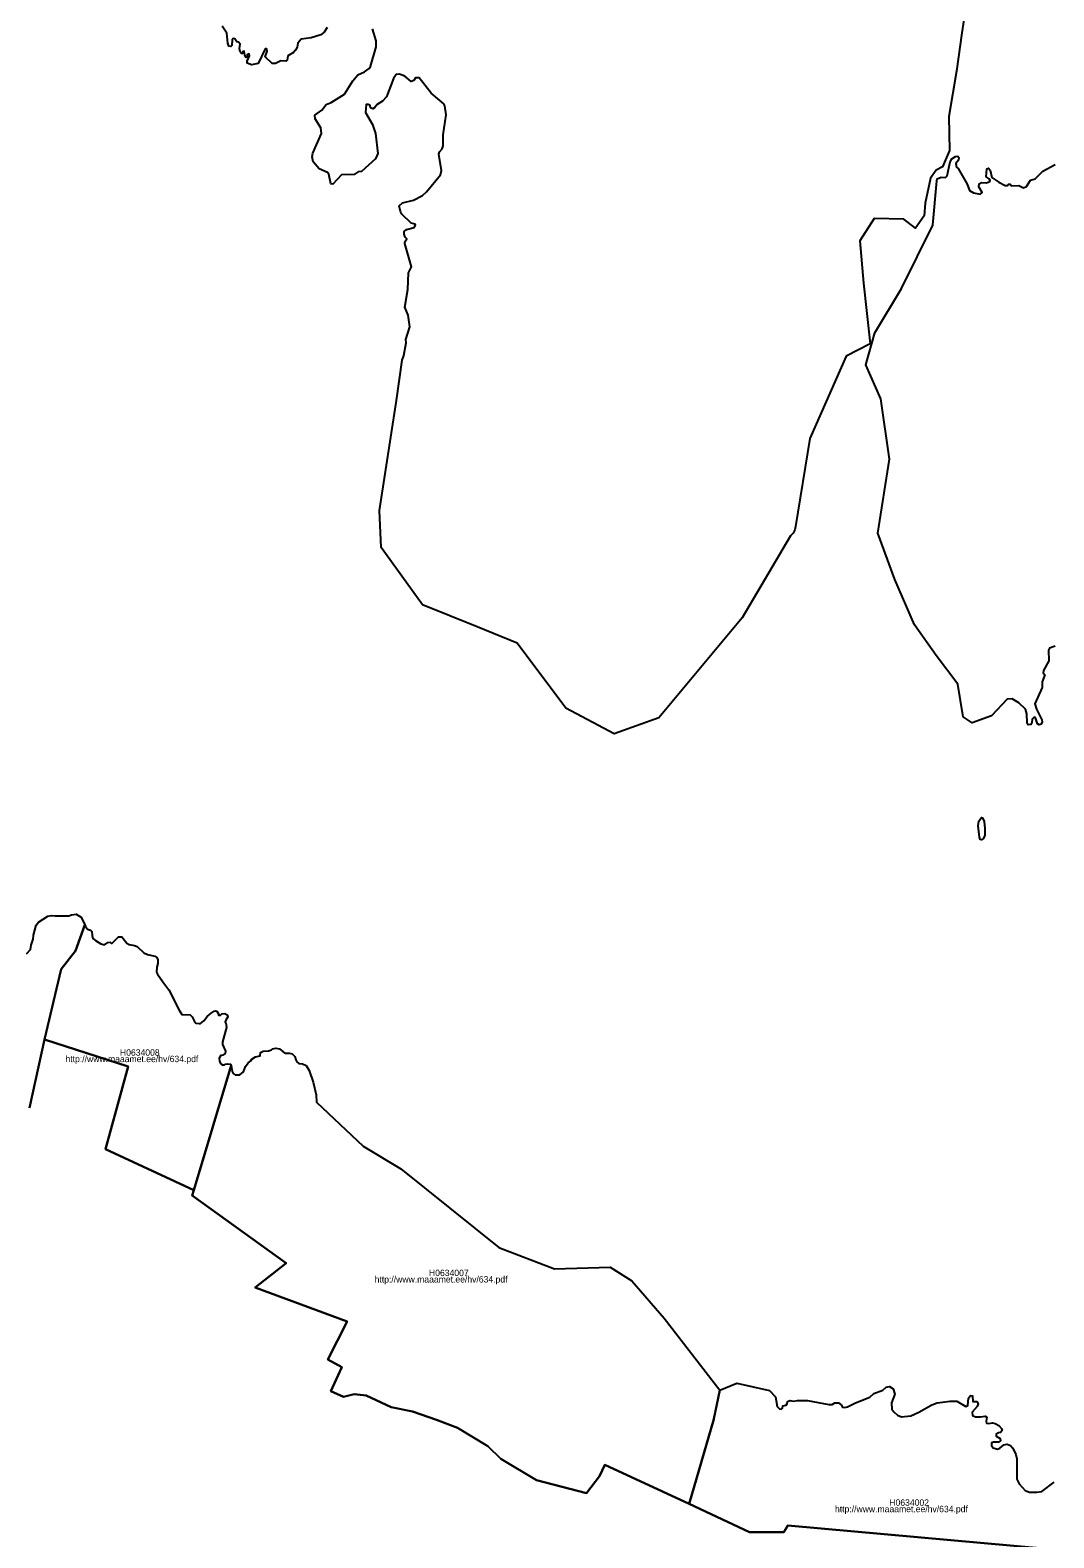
# Model space of a CAD drawing. Extents: x 369010 to 739155, y 6377141 to 6634081.
# Drawn here: x 452935 to 456915, y 6483613 to 6489475 of the extents above; entities that cross this region are included whole.
import ezdxf

# ---------------------------------------------------------------- set-up
doc = ezdxf.new("R2010")
doc.units = 0
for name, color, linetype in [('H_LINK', 7, 'Continuous'), ('H_PIIR', 7, 'Continuous'), ('H_TUNNUS', 7, 'Continuous')]:
    doc.layers.add(name, color=color, linetype=linetype)

msp = doc.modelspace()

# ---------------------------------------------------------------- linework, layer by layer
at = {"layer": 'H_PIIR'}
for points in [[(456585.5297, 6489652.0638), (456556.9546, 6489464.7385), (456536.3171, 6489315.5132), (456506.1545, 6489139.3003), (456508.74, 6489007.06), (456482.342, 6488944.0374), (456456.9419, 6488931.3374), (456434.7169, 6488899.5873), (456414.8026, 6488803.0723), (456410.9725, 6488753.5823), (456377.5668, 6488705.9119), (456331.5292, 6488740.837), (456215.6415, 6488742.4245), (456160.0788, 6488656.6993), (456174.3664, 6488491.599), (456200.86, 6488255.74), (456107.84, 6488207.24), (455966.4035, 6487887.554), (455910.7401, 6487545.0001), (455908.18, 6487532.1699), (455901.12, 6487519.33), (455891.18, 6487509.39), (455703.1425, 6487190.6402), (455379.2919, 6486801.1727), (455205.7249, 6486739.7893), (455017.3411, 6486839.2728), (454828.9574, 6487091.1566), (454672.3238, 6487154.6567), (454460.6567, 6487241.4403), (454299.7897, 6487463.6907), (454293.4397, 6487607.6243), (454359.0565, 6488035.1918), (454380.75, 6488191.7801), (454388.1201, 6488209.74), (454396.1401, 6488259.7901), (454394.8599, 6488271.9801), (454411.2201, 6488321.3899), (454404.49, 6488367.5899), (454391.9699, 6488398.38), (454403.84, 6488467.04), (454406.4099, 6488531.2), (454417.9599, 6488554.6201), (454391.33, 6488645.42), (454391.65, 6488652.48), (454399.35, 6488663.7001), (454392.6199, 6488670.1201), (454388.77, 6488681.99), (454389.41, 6488692.26), (454397.7499, 6488699.64), (454427.2601, 6488708.6199), (454433.6801, 6488716.96), (454431.7599, 6488720.49), (454416.68, 6488725.2999), (454379.78, 6488759.9499), (454374.6499, 6488769.58), (454369.84, 6488791.7099), (454382.67, 6488803.9001), (454424.7, 6488814.8099), (454460.31, 6488832.46), (454475.7099, 6488846.5701), (454530.89, 6488912.3401), (454534.1001, 6488929.0199), (454523.83, 6488992.5501), (454526.72, 6489002.8099), (454536.9901, 6489013.4001), (454540.19, 6489025.9099), (454540.52, 6489068.26), (454552.71, 6489145.8999), (454547.2499, 6489181.1899), (454543.08, 6489188.2501), (454493.6801, 6489230.6), (454447.8, 6489289.31), (454433.0401, 6489289.31), (454426.3, 6489280), (454415.7201, 6489275.8299), (454391.0101, 6489296.6901), (454370.8001, 6489304.0599), (454358.29, 6489302.4601), (454348.02, 6489287.06), (454320.4299, 6489216.4801), (454304.71, 6489198.84), (454283.86, 6489186.64), (454273.91, 6489172.85), (454267.82, 6489169.32), (454257.87, 6489173.1701), (454256.27, 6489182.15), (454249.5299, 6489186.3199), (454241.5101, 6489186.3199), (454239.2601, 6489155.52), (454265.89, 6489108.68), (454277.1199, 6489073.3901), (454286.1, 6488995.76), (454277.44, 6488975.2199), (454223.5399, 6488925.4999), (454209.7501, 6488924.85), (454194.35, 6488913.9499), (454145.9, 6488912.66), (454112.2199, 6488877.0499), (454104.52, 6488877.37), (454095.5401, 6488915.55), (454090.72, 6488922.29), (454058.6401, 6488936.72), (454035.22, 6488962.71), (454031.05, 6488982.28), (454033.62, 6488996.4), (454068.2599, 6489074.04), (454064.4201, 6489095.2099), (454042.9199, 6489130.5001), (454041.3201, 6489144.9401), (454068.59, 6489164.19), (454085.91, 6489186.3199), (454105.16, 6489193.7), (454156.49, 6489226.7499), (454188.8999, 6489277.76), (454209.1099, 6489301.1799), (454235.41, 6489313.69), (454252.4199, 6489326.2), (454258.51, 6489334.54), (454279.69, 6489410.9001), (454280.6499, 6489434.0001), (454266.2099, 6489480.2001)], [(454090.08, 6489485.65), (454077.89, 6489467.04), (454065.3799, 6489457.1001), (454026.8801, 6489444.9001), (453988.38, 6489440.41), (453975.87, 6489425.3401), (453972.6601, 6489409.6199), (453966.2399, 6489397.42), (453958.8601, 6489389.08), (453937.3699, 6489375.6099), (453934.16, 6489359.25), (453929.9901, 6489354.11), (453910.1, 6489356.36), (453888.9299, 6489345.45), (453876.41, 6489345.1301), (453849.1401, 6489371.44), (453856.84, 6489393.5701), (453855.5601, 6489401.27), (453852.35, 6489403.2), (453848.18, 6489402.56), (453821.23, 6489345.45), (453795.25, 6489340), (453779.1999, 6489347.3801), (453778.2401, 6489354.43), (453788.19, 6489375.6099), (453786.9001, 6489382.34), (453782.0899, 6489383.6299), (453778.88, 6489381.06), (453777.6001, 6489370.15), (453774.7101, 6489369.51), (453769.9, 6489377.53), (453766.6901, 6489393.5701), (453761.8799, 6489392.9299), (453759.96, 6489383.95), (453756.7499, 6489383.95), (453751.87, 6489390.83), (453748.7301, 6489403.8399), (453751.29, 6489421.49), (453745.1999, 6489428.2201), (453738.78, 6489429.51), (453730.7599, 6489442.0201), (453724.34, 6489443.3), (453719.8499, 6489437.21), (453718.89, 6489415.71), (453715.68, 6489411.86), (453707.6599, 6489413.46), (453703.49, 6489425.02), (453699.6399, 6489463.51), (453681.03, 6489490.78)], [(456920.2999, 6487080.68), (456897.62, 6487072.7), (456893.7899, 6487065.04), (456895.39, 6487023.1999), (456874.3101, 6486985.1999), (456873.35, 6486976.5801), (456879.4199, 6486968.6001), (456869.84, 6486940.8201), (456869.2, 6486919.74), (456840.7801, 6486856.5199), (456847.49, 6486835.44), (456867.61, 6486793.29), (456868.88, 6486786.2701), (456865.0501, 6486777.0001), (456857.71, 6486774.45), (456851, 6486778.5999), (456843.98, 6486800.95), (456838.5501, 6486803.5101), (456829.9101, 6486796.87), (456829.55, 6486783.2399), (456825.46, 6486775.7299), (456815.56, 6486773.81), (456811.08, 6486781.8), (456809.17, 6486816.92), (456804.06, 6486835.44), (456778.5101, 6486859.3899), (456752.33, 6486875.6801), (456733.17, 6486874.08), (456672.8424, 6486808.8456), (456596.6422, 6486781.8581), (456561.7172, 6486805.6706), (456541.0796, 6486932.6709), (456456.9419, 6487043.7961), (456372.8043, 6487162.8588), (456296.6041, 6487339.0717), (456229.929, 6487520.0471), (456275.9666, 6487807.3851), (456242.629, 6488042.3356), (456183.8914, 6488174.0984), (456218.8165, 6488297.9236), (456322.0042, 6488470.9615), (456444.2419, 6488717.0245), (456460.4699, 6488889.3401), (456461.42, 6488897), (456476.43, 6488903.39), (456493.04, 6488901.8), (456500.3801, 6488909.4601), (456511.8799, 6488962.79), (456518.2601, 6488974.5999), (456531.9999, 6488984.5001), (456541.2599, 6488984.82), (456545.4301, 6488980.26), (456544.45, 6488970.1301), (456533.95, 6488956.58), (456536.1501, 6488942.9901), (456543.27, 6488937.92), (456577.34, 6488875.9299), (456587.04, 6488851.8101), (456602.89, 6488842.72), (456627.7899, 6488837.9301), (456635.65, 6488844.63), (456622.7301, 6488866.52), (456623.96, 6488877.84), (456633.86, 6488882.67), (456652.38, 6488881.36), (456665.4701, 6488887.11), (456666.75, 6488890.9399), (456663.27, 6488897.3801), (456651.4299, 6488905.27), (456653.7699, 6488936.42), (456660.35, 6488938.17), (456666.7, 6488930.7099), (456674.1001, 6488901.8), (456700.92, 6488884.23), (456725.51, 6488871.78), (456734.1301, 6488871.78), (456737.9599, 6488876.89), (456744.3499, 6488876.5701), (456750.7299, 6488869.5399), (456778.2, 6488871.14), (456797.04, 6488861.88), (456808.85, 6488867.9501), (456824.18, 6488891.9), (456842.3799, 6488896.6899), (456871.4401, 6488927.02), (456919.3401, 6488953.2099)], [(452921.3299, 6485883.4647), (452935.7601, 6485900.4746), (452938.6501, 6485917.7946), (452946.6699, 6485940.8946), (452948.28, 6485956.2946), (452957.9, 6485994.7947), (452966.8799, 6486006.6646), (453003.46, 6486030.4047), (453017.5699, 6486032.9646), (453031.69, 6486031.0447), (453085.2701, 6486031.0447), (453095.21, 6486035.8546), (453113.82, 6486038.1047), (453133.0699, 6486026.8746), (453146.8989, 6485996.6055), (453111.2501, 6485896.06), (453056.02, 6485823.7801), (452990.1101, 6485550.08), (452932.49, 6485285.4801)], [(452932.49, 6485285.4801), (452990.1101, 6485550.08), (453316.0201, 6485445.2399), (453227.27, 6485123.9101), (453570.9099, 6484965.4), (453564.54, 6484944.17), (453930.4299, 6484681.3299), (453809.7, 6484586.4), (454167.7101, 6484454.0101), (454092.26, 6484306.65), (454147.27, 6484277.16), (454104.0499, 6484182.8099), (454153.1699, 6484161.19), (454194.45, 6484172.2), (454241.14, 6484165.84), (454338.77, 6484121.25), (454421.5401, 6484104.2599), (454514.9299, 6484072.42), (454595.99, 6484041.13), (454714.31, 6483969.17), (454764.92, 6483920.52), (454903.8901, 6483836.6199), (455097.3, 6483786.64), (455148.23, 6483852.46), (455169.46, 6483897.05), (455496.3699, 6483744.73), (455731.08, 6483635.3701), (455865.6901, 6483634.6901), (455880.86, 6483661.38), (456889.11, 6483570.5799)], [(456889.11, 6483570.5799), (455880.86, 6483661.38), (455865.6901, 6483634.6901), (455731.08, 6483635.3701), (455496.3699, 6483744.73), (455592.6399, 6484074.69), (455593.0409, 6484076.0639), (455616.7729, 6484187.3525), (455682.0458, 6484215.0545), (455809.28, 6484185.4446), (455832.1999, 6484161.4046), (455838.5499, 6484123.2946), (455847.62, 6484114.2247), (455854.88, 6484113.7647), (455859.8699, 6484116.9446), (455860.78, 6484126.9247), (455874.3801, 6484128.7347), (455878.4701, 6484135.0947), (455879.83, 6484142.8046), (455890.26, 6484147.3447), (455900.7, 6484144.6146), (455917.93, 6484147.3447), (455957.17, 6484146.8846), (456040.18, 6484131.0047), (456052.43, 6484131.0047), (456063.77, 6484138.2646), (456076.9301, 6484138.2646), (456088.04, 6484130.5547), (456093.4899, 6484121.4846), (456102.11, 6484119.2146), (456112.0901, 6484121.9347), (456143.8401, 6484138.2746), (456199.91, 6484160.6246), (456214.62, 6484173.7847), (456250.0401, 6484187.3346), (456263.1999, 6484199.3346), (456275.58, 6484201.6546), (456289.9, 6484191.9746), (456296.48, 6484172.2346), (456284.1001, 6484138.1746), (456285.26, 6484113.7847), (456292.22, 6484102.9446), (456307.32, 6484089.7846), (456322.41, 6484083.2047), (456359.38, 6484087.4646), (456390.34, 6484101.0147), (456441.0401, 6484130.4347), (456461.7501, 6484137.3947), (456511.68, 6484144.3647), (456537.2199, 6484143.9746), (456572.06, 6484123.8546), (456580.96, 6484127.3346), (456583.28, 6484156.3647), (456590.4401, 6484166.4246), (456598.18, 6484165.2646), (456600.1199, 6484143.2047), (456614.83, 6484142.8146), (456621.0201, 6484133.9147), (456616.76, 6484123.4647), (456597.02, 6484101.3946), (456598.57, 6484088.6246), (456610.5701, 6484083.9746), (456629.15, 6484083.2047), (456648.1101, 6484085.9146), (456654.69, 6484081.6546), (456651.21, 6484066.1746), (456652.37, 6484059.2046), (456660.5, 6484058.0446), (456676.3701, 6484060.3646), (456687.1999, 6484057.6546), (456700.75, 6484049.9146), (456710.81, 6484037.9146), (456713.9101, 6484029.7846), (456707.72, 6484022.8146), (456699.59, 6484020.8847), (456691.07, 6484016.6246), (456690.3, 6484008.4946), (456706.17, 6483998.8147), (456707.91, 6483990.6846), (456699.01, 6483985.6547), (456680.4301, 6483985.2646), (456671.92, 6483982.9446), (456672.3001, 6483972.4947), (456678.5, 6483962.8146), (456695.14, 6483958.1746), (456705.2001, 6483961.2646), (456720.3001, 6483974.8147), (456733.84, 6483976.7546), (456745.84, 6483971.7247), (456755.8999, 6483961.6546), (456767.5101, 6483936.4946), (456771.38, 6483919.8547), (456771.19, 6483841.2746), (456780.48, 6483823.0747), (456803.7, 6483796.7546), (456819.9599, 6483790.5647), (456848.6, 6483790.5647), (456867.57, 6483793.6547), (456916.52, 6483828.8746)]]:
    msp.add_lwpolyline(points, dxfattribs=at)
for points in [[(456641.2001, 6486332.5), (456633.22, 6486326.76), (456628.75, 6486328.35), (456625.88, 6486337.3001), (456620.4501, 6486382), (456622.6801, 6486399.88), (456632.9, 6486414.25), (456637.37, 6486412.9701), (456644.4, 6486398.6), (456646.9501, 6486371.7799), (456645.99, 6486345.6)], [(453146.8989, 6485996.6055), (453150.07, 6485989.6646), (453157.45, 6485979.0747), (453169, 6485976.1847), (453175.0999, 6485971.0547), (453175.7399, 6485955.6546), (453178.3, 6485943.7846), (453188.89, 6485935.1146), (453210.07, 6485923.2447), (453224.1799, 6485919.3946), (453236.7, 6485927.7447), (453246.32, 6485928.7046), (453250.1699, 6485925.1746), (453254.02, 6485924.8547), (453279.0399, 6485950.1947), (453290.91, 6485949.5546), (453310.48, 6485925.4947), (453319.79, 6485919.7247), (453340.64, 6485916.8347), (453350.5899, 6485912.3446), (453377.54, 6485887.9547), (453391.6501, 6485881.2246), (453419.8801, 6485874.1647), (453426.94, 6485869.3546), (453431.76, 6485860.3647), (453431.11, 6485846.5746), (453426.94, 6485832.4546), (453426.62, 6485812.8847), (453430.47, 6485804.2247), (453450.3599, 6485774.7046), (453473.78, 6485744.2347), (453514.21, 6485664.9846), (453524.47, 6485648.3046), (453556.5599, 6485646.7047), (453565.2199, 6485638.3546), (453571.95, 6485623.2846), (453578.69, 6485614.6147), (453591.8401, 6485612.3746), (453596.66, 6485613.3347), (453610.45, 6485623.6047), (453623.29, 6485640.2846), (453639.0099, 6485653.4346), (453650.88, 6485661.1347), (453657.29, 6485662.7446), (453660.18, 6485661.4546), (453668.2, 6485647.6646), (453667.24, 6485645.7347), (453675.26, 6485645.4146), (453680.39, 6485650.5546), (453691.94, 6485651.5147), (453701.24, 6485646.0546), (453703.1701, 6485638.3546), (453695.1501, 6485626.4847), (453693.55, 6485618.7846), (453695.47, 6485615.5847), (453698.68, 6485597.6146), (453682.64, 6485541.1547), (453682.3199, 6485531.5247), (453693.8699, 6485505.8646), (453692.9, 6485496.2347), (453684.24, 6485490.1446), (453676.86, 6485488.2147), (453669.6599, 6485478.0346), (453670.45, 6485464.7046), (453676.86, 6485456.1346), (453682.64, 6485452.2847), (453690.9799, 6485452.2847), (453693.54, 6485454.5246), (453703.49, 6485456.1346), (453713.4399, 6485454.8446), (453716.8899, 6485449.1999), (453570.9099, 6484965.4), (453227.27, 6485123.9101), (453316.0201, 6485445.2399), (452990.1101, 6485550.08), (453056.02, 6485823.7801), (453111.2501, 6485896.06)], [(453716.8912, 6485449.2036), (453716.9699, 6485449.0746), (453719.8499, 6485425.6546), (453724.0201, 6485418.5946), (453732.0401, 6485413.7847), (453750.01, 6485413.7847), (453764.7699, 6485425.0146), (453772.15, 6485445.5447), (453782.41, 6485459.3447), (453792.6801, 6485468.0047), (453796.5299, 6485474.4146), (453810.5701, 6485483.6546), (453828.9501, 6485487.4247), (453830.86, 6485499.7647), (453840.8, 6485505.5347), (453861.98, 6485506.8246), (453873.8499, 6485510.3546), (453877.3799, 6485513.8846), (453889.5701, 6485516.7646), (453904.33, 6485514.8446), (453919.08, 6485502.6547), (453928.0699, 6485498.1646), (453942.82, 6485498.1646), (453954.0499, 6485494.6346), (453963.68, 6485484.3646), (453967.21, 6485471.2146), (453971.3799, 6485464.1546), (453979.3999, 6485457.4146), (453993.51, 6485456.1346), (454007.63, 6485449.0746), (454020.14, 6485430.7846), (454035.86, 6485384.5846), (454046.77, 6485335.1847), (454048.6999, 6485306.9547), (454229.9601, 6485135.3146), (454376.051, 6485048.132), (454756.5314, 6484742.1055), (454974.0194, 6484659.5554), (455189.9198, 6484665.9054), (455274.0575, 6484611.9303), (455399.4702, 6484467.4675), (455616.7729, 6484187.3525), (455593.0409, 6484076.0639), (455592.6399, 6484074.69), (455496.3699, 6483744.73), (455169.46, 6483897.05), (455148.23, 6483852.46), (455097.3, 6483786.64), (454903.8901, 6483836.6199), (454764.92, 6483920.52), (454714.31, 6483969.17), (454595.99, 6484041.13), (454514.9299, 6484072.42), (454421.5401, 6484104.2599), (454338.77, 6484121.25), (454241.14, 6484165.84), (454194.45, 6484172.2), (454153.1699, 6484161.19), (454104.0499, 6484182.8099), (454147.27, 6484277.16), (454092.26, 6484306.65), (454167.7101, 6484454.0101), (453809.7, 6484586.4), (453930.4299, 6484681.3299), (453564.54, 6484944.17), (453570.9099, 6484965.4)]]:
    msp.add_lwpolyline(points, close=True, dxfattribs=at)

# ---------------------------------------------------------------- texts
at = {"layer": 'H_LINK'}
for rotation, p in [(360, (453072.2759, 6485462.6976)), (360, (454274.1885, 6484605.7473)), (0, (456063.8657, 6483712.6623))]:
    msp.add_text('http://www.maaamet.ee/hv/634.pdf', height=25, rotation=rotation, dxfattribs=at).set_placement(p)
at = {"layer": 'H_TUNNUS'}
for s, rotation, p in [('H0634008', 360, (453284.1305, 6485487.6976)), ('H0634007', 360, (454485.4174, 6484630.7473)), ('H0634002', 0, (456275.0946, 6483737.6623))]:
    msp.add_text(s, height=25, rotation=rotation, dxfattribs=at).set_placement(p)

doc.saveas('drawing.dxf')
